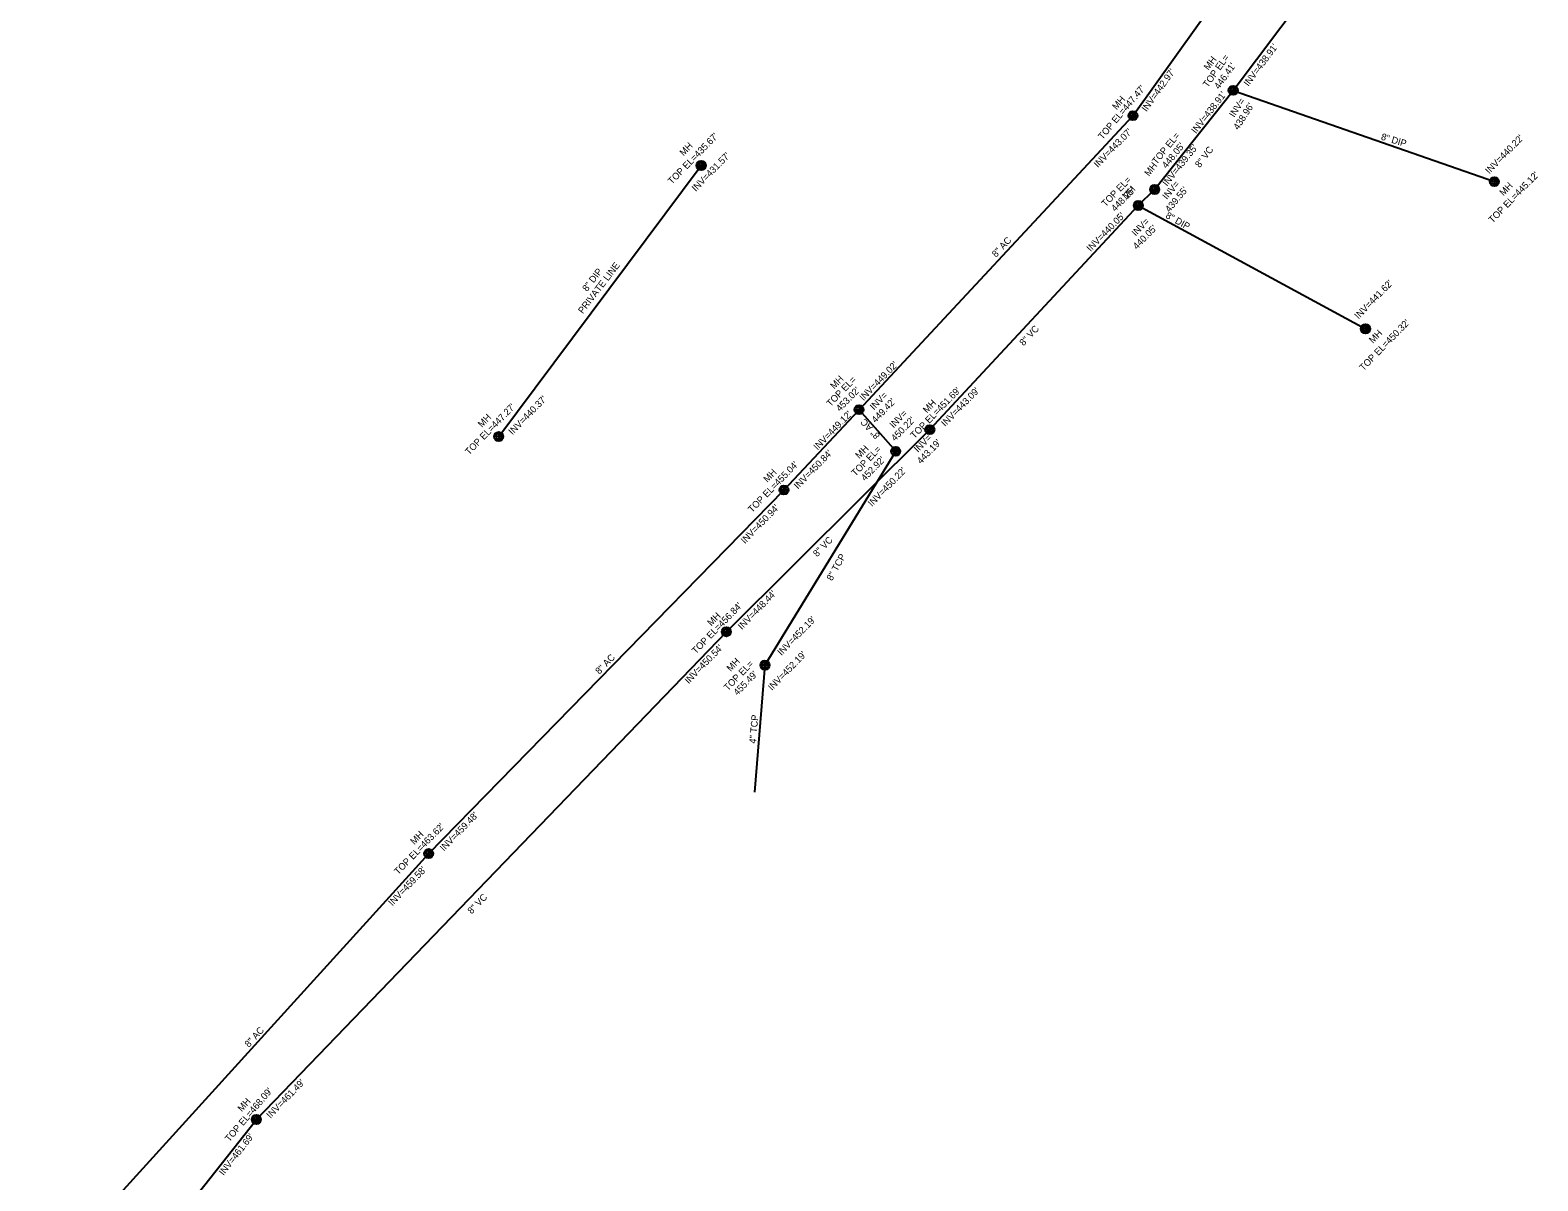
# Model space of a CAD drawing. Extents: x 1975698 to 1978521, y 778259 to 782969.
# Drawn here: x 1976397 to 1977286, y 779600 to 780279 of the extents above; entities that cross this region are included whole.
import ezdxf

# ---------------------------------------------------------------- set-up
doc = ezdxf.new("R2010")
doc.units = 0
for name, color, linetype in [('Old_Level_11', 7, 'Continuous'), ('Prop Horizontal Alignment', 7, 'Continuous'), ('Prop Horizontal Alignment Station Label', 7, 'Continuous'), ('Prop WCC CELL', 7, 'Continuous')]:
    doc.layers.add(name, color=color, linetype=linetype)

# ---------------------------------------------------------------- blocks, each defined once
blk = doc.blocks.new('EXIST UTILITIES SANITARY SEWER MANHOLE')
at = {"layer": 'Prop Horizontal Alignment'}
blk.add_lwpolyline([(0, 0.034), (0, -0.034), (0, 0), (0.034, 0), (-0.034, 0)], dxfattribs=at)
for radius in [0.0539, 0.0342]:
    blk.add_circle((0, 0), radius, dxfattribs=at)

msp = doc.modelspace()

# ---------------------------------------------------------------- linework, layer by layer
at = {"layer": 'Prop Horizontal Alignment Station Label'}
for p, q in [((1977046.91, 780228.38), (1977177.86, 780411.19)), ((1977106, 780243.3), (1977180.4, 780342.25)), ((1977059.69, 780184.88), (1977106, 780243.3)), ((1977106, 780243.3), (1977260.05, 780189.52)), ((1976885.43, 780054.99), (1977046.91, 780228.38)), ((1977050.05, 780175.43), (1977059.69, 780184.88)), ((1976927.13, 780043.28), (1977050.05, 780175.43)), ((1977050.05, 780175.43), (1977184.06, 780102.69)), ((1976841.15, 780007.61), (1976885.43, 780054.99)), ((1976885.43, 780054.99), (1976907.03, 780030.49)), ((1976807.22, 779924.05), (1976927.13, 780043.28)), ((1976907.03, 780030.49), (1976829.96, 779904.34)), ((1976631.67, 779793.27), (1976841.15, 780007.61)), ((1976530.08, 779636.44), (1976807.22, 779924.05)), ((1976829.96, 779904.34), (1976823.86, 779829.48)), ((1976431.23, 779572.58), (1976631.67, 779793.27)), ((1976396.69, 779467.91), (1976530.08, 779636.44))]:
    msp.add_line(p, q, dxfattribs=at)
msp.add_lwpolyline([(1976672.96, 780039.17), (1976792.35, 780199.01)], dxfattribs=at)

# ---------------------------------------------------------------- block references
at = {"layer": 'Prop Horizontal Alignment', "xscale": 50, "yscale": 50}
for p in [(1977106, 780243.3), (1977046.91, 780228.38), (1976792.35, 780199.01), (1977059.69, 780184.88), (1977260.05, 780189.52), (1977050.05, 780175.43), (1977184.06, 780102.69), (1976885.43, 780054.99), (1976672.96, 780039.17), (1976927.13, 780043.28), (1976907.03, 780030.49), (1976841.15, 780007.61), (1976807.22, 779924.05), (1976829.96, 779904.34), (1976631.67, 779793.27), (1976530.08, 779636.44)]:
    msp.add_blockref('EXIST UTILITIES SANITARY SEWER MANHOLE', p, dxfattribs=at)

# ---------------------------------------------------------------- texts
at = {"layer": 'Old_Level_11'}
for s, rotation, p in [('8" DIP', 343.24736, (1977192.9, 780214.31)), ('8" DIP', 330.98922, (1977065.77, 780168.34)), ('8" AC', 46.98587, (1976966.21, 780144.58)), ('8" VC', 46.98587, (1976982.48, 780092.38)), ('8" AC', 132.39491, (1976898.09, 780039.95)), ('8" VC', 46.06185, (1976860.72, 779967.95)), ('8" TCP', 61.0315, (1976869.48, 779953.75)), ('8" AC', 46.06185, (1976732.32, 779898.69)), ('4" TCP', 85.0529, (1976824.63, 779858)), ('8" VC', 46.06185, (1976657, 779757.31)), ('8" AC', 47.75165, (1976525.65, 779678.69))]:
    msp.add_text(s, height=4, rotation=rotation, dxfattribs=at).set_placement(p)
at = {"layer": 'Prop WCC CELL'}
for s, rotation, p in [('TOP EL=', 54.36106, (1977091.03, 780244.68)), ("INV=438.91'", 53.11808, (1977114.99, 780245.39)), ("INV=442.97'", 54.3615, (1977054.93, 780230.38)), ('MH', 52.52877, (1977091.45, 780254.89)), ("446.41'", 54.36106, (1977097.67, 780243.64)), ("TOP EL=447.47'", 49.97843, (1977029.02, 780213.97)), ('MH', 48.99151, (1977037.26, 780231.58)), ("INV=438.91'", 52.01486, (1977084.1, 780217.48)), ('INV=', 57.05603, (1977106.68, 780227.04)), ("438.96'", 57.05603, (1977109.06, 780219.68)), ("INV=443.07'", 45.73946, (1977026.23, 780197.47)), ("TOP EL=435.67'", 45.73946, (1976775.11, 780187.57)), ('MH', 45.73946, (1976781.95, 780204.33)), ('TOP EL=', 50.8531, (1977060.89, 780199.36)), ("INV=439.35'", 51.50657, (1977067.07, 780186.44)), ("448.05'", 50.8531, (1977066.7, 780196.99)), ("INV=440.22'", 45.73946, (1977257.06, 780193.73)), ("INV=431.57'", 45.73946, (1976789.18, 780183.37)), ('8" VC', 53.16099, (1977086.35, 780197.38)), ('MH', 52.29091, (1977056.43, 780192.35)), ("TOP EL=445.12'", 45.73946, (1977258.98, 780164.75)), ('TOP EL=', 45.73946, (1977030.78, 780174.32)), ("448.25'", 45.73946, (1977036.46, 780171.55)), ('MH', 45.73946, (1977042.97, 780178.75)), ('INV=', 50.31644, (1977067, 780178.63)), ("439.55'", 50.31644, (1977068.56, 780171.12)), ('MH', 45.73946, (1977265.4, 780180.82)), ("INV=440.05'", 45.73946, (1977021.98, 780147.94)), ('INV=', 45.73946, (1977048.54, 780157.04)), ("440.05'", 45.73946, (1977049.28, 780149.2)), ('PRIVATE LINE', 52.45479, (1976722.56, 780111.28)), ('8" DIP', 52.45479, (1976725.06, 780124.38)), ("INV=441.62'", 45.73946, (1977179.95, 780108.12)), ("TOP EL=450.32'", 45.73946, (1977182.85, 780077.63)), ('MH', 45.73946, (1977188.45, 780093.87)), ("INV=449.02'", 45.73946, (1976888.06, 780060.02)), ('TOP EL=', 45.73946, (1976868.63, 780056.5)), ('MH', 45.73946, (1976870.85, 780066.86)), ("453.02'", 45.73946, (1976874.2, 780053.62)), ("TOP EL=451.69'", 45.73946, (1976918.08, 780037.66)), ("INV=440.37'", 45.73946, (1976681.12, 780039.88)), ('INV=', 45.73946, (1976894.22, 780054.53)), ("449.42'", 45.73946, (1976895.18, 780046.91)), ('MH', 45.73946, (1976925.5, 780052.66)), ("INV=443.09'", 45.73946, (1976936.25, 780044.77)), ("TOP EL=447.27'", 45.73946, (1976655.5, 780027.98)), ('MH', 45.73946, (1976663.09, 780044.25)), ("INV=449.12'", 45.73946, (1976860.99, 780030.87)), ('INV=', 45.73946, (1976905.82, 780043.86)), ("450.22'", 45.73946, (1976906.67, 780036.13)), ('TOP EL=', 45.73946, (1976883.29, 780015.45)), ('MH', 45.73946, (1976885.63, 780025.82)), ('INV=', 45.73946, (1976920.19, 780029.52)), ("443.19'", 45.73946, (1976921.94, 780022.72)), ("TOP EL=455.04'", 45.73946, (1976822.36, 779994.01)), ("INV=450.84'", 45.73946, (1976849.43, 780007.92)), ("452.92'", 45.73946, (1976888.97, 780012.68)), ('MH', 45.73946, (1976831.37, 780011.83)), ("INV=450.22'", 45.73946, (1976893.05, 779997.6)), ("INV=450.94'", 45.73946, (1976818.11, 779975.69)), ("INV=448.44'", 45.73946, (1976816.37, 779925.04)), ("TOP EL=456.84'", 45.73946, (1976789.23, 779910.65)), ('MH', 45.73946, (1976798.39, 779927.17)), ("INV=452.19'", 45.73946, (1976839.67, 779909.77)), ("INV=450.54'", 45.73946, (1976784.99, 779893.07)), ('MH', 45.73946, (1976809.75, 779900.32)), ("INV=452.19'", 45.73946, (1976834.09, 779889.13)), ('TOP EL=', 45.73946, (1976808.07, 779888.94)), ("455.49'", 45.73946, (1976813.75, 779886.17)), ("TOP EL=463.62'", 45.73946, (1976613.72, 779780.5)), ("INV=459.48'", 45.73946, (1976640.68, 779794.37)), ('MH', 45.73946, (1976623.21, 779798.26)), ("INV=459.58'", 46.3896, (1976610.3, 779762.08)), ("INV=461.49'", 45.73946, (1976538.38, 779636.8)), ("TOP EL=468.09'", 49.59697, (1976514.18, 779622.96)), ('MH', 48.3432, (1976521.5, 779640.75)), ("INV=461.69'", 51.9124, (1976510.73, 779603.14))]:
    msp.add_text(s, height=4, rotation=rotation, dxfattribs=at).set_placement(p)

doc.saveas('drawing.dxf')
